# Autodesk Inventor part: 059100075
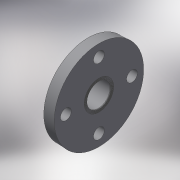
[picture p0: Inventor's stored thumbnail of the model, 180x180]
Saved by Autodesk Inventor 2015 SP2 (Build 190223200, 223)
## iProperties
Created: 2017-10
Part Number: 059100075
Material: Generic
Description: PLASSON FIXED FLANGE-CEM PVC 75
Document SubType Name: Modeling
Designer: KIM
Density: 1 g/cm^3
Appearance: Default
Author: KIM
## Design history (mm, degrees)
derived "059200.ipt"
feature "Solid1::059200.ipt"
tag "TaggingFeature1"
body "Solid1"
other parameters: "d0" = 47, "d2" = 185, "d3" = 183.15, "d14" = 18, "d15" = 72.5, "d16" = 47, "d17" = 0, "d19" = 360 deg, "d21" = 44, "d22" = 75, "d23" = 71.25, "d25" = 0.75, "d26" = 0.925, "d27" = 0.925, "d28" = 0.925, "d29" = 0.925, "d30" = 0.925, "d31" = 0.925, "d32" = 0.37, "d33" = 0, "d34" = 19, "E_" = 185, "H_" = 47, "Dp_" = 145, "S_" = 18, "l_" = 44, "d_" = 75, "H_1" = 19
